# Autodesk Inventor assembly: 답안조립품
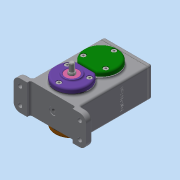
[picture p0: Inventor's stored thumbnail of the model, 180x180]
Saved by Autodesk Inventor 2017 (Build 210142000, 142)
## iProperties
Part Number: 답안조립품
Material: 일반
Document SubType Name: Assembly
Designer: mrc
Author: mrc
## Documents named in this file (24)
- C:\Users\mrc\Desktop\600506V1021\답안조립품.iam
- C:\Users\mrc\Desktop\600506V1021\본체.ipt
- C:\Users\mrc\Desktop\600506V1021\개스킷 A.ipt
- C:\Users\mrc\Desktop\600506V1021\개스킷 B.ipt
- C:\Users\mrc\Desktop\600506V1021\개스킷 C.ipt
- C:\Users\mrc\Desktop\600506V1021\베어링 6001.ipt
- 베어링 6001.ipt
- C:\Users\mrc\Desktop\600506V1021\베어링 6002.ipt
- 베어링 6002.ipt
- C:\Users\mrc\Desktop\600506V1021\볼트 M4.ipt
- C:\Users\mrc\Desktop\600506V1021\스퍼기어 A.ipt
- C:\Users\mrc\Desktop\600506V1021\스퍼기어 B.ipt
- C:\Users\mrc\Desktop\600506V1021\오일 실 10 20 7.ipt
- C:\Users\mrc\Desktop\600506V1021\오일 실 12 22 7.ipt
- C:\Users\mrc\Desktop\600506V1021\축 A.ipt
- C:\Users\mrc\Desktop\600506V1021\축 B.ipt
- C:\Users\mrc\Desktop\600506V1021\칼라.ipt
- C:\Users\mrc\Desktop\600506V1021\커버 A.ipt
- C:\Users\mrc\Desktop\600506V1021\커버 B.ipt
- C:\Users\mrc\Desktop\600506V1021\커버 C.ipt
- C:\Users\mrc\Desktop\600506V1021\커버 D.ipt
- C:\Users\mrc\Desktop\600506V1021\커버 E.ipt
- C:\Users\mrc\Desktop\600506V1021\키 4 x 4 x 12.ipt
- C:\Users\mrc\Desktop\600506V1021\키 5 x 5 x 12.ipt
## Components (5 placed, 3 different names)
1. 개스킷 A:1 — 플러쉬:1
2. 개스킷 C:1
3. 개스킷 A:2 — 플러쉬:3
4. 개스킷 A:3 — 플러쉬:2
5. 개스킷 B:1
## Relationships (3: Flush 3)
- 플러쉬:1 [Flush]: 개스킷 A:1
- 플러쉬:2 [Flush]: 개스킷 A:3
- 플러쉬:3 [Flush]: 개스킷 A:2
